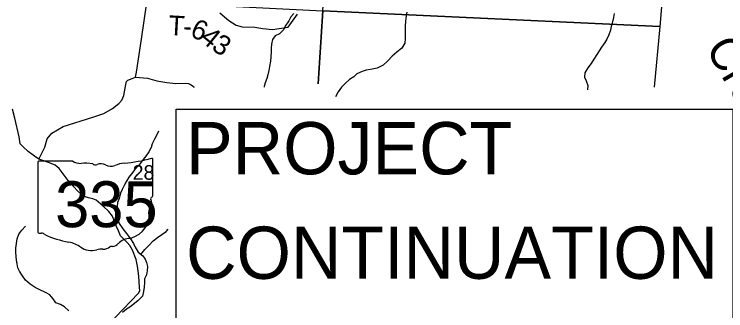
# Model space of a CAD drawing. Extents: x 0 to 40.8, y 0 to 22.
# Drawn here: x 4.714 to 6.756, y 18.326 to 19.177 of the extents above; entities that cross this region are included whole.
import ezdxf

# ---------------------------------------------------------------- set-up
doc = ezdxf.new("R2010")
doc.units = 0
for name, color, linetype in [('Default', 7, 'Continuous'), ('GM_X_County_Road', 7, 'Continuous'), ('GM_X_Minor_River', 7, 'Continuous'), ('GM_X_Minor_River_Text', 7, 'Continuous'), ('GM_X_Section', 7, 'Continuous'), ('GM_X_Section_Text', 7, 'Continuous'), ('GM_X_State_Location', 7, 'Continuous'), ('GM_X_State_Route', 7, 'Continuous'), ('GM_X_State_Shield', 7, 'Continuous'), ('GM_X_Township_Road', 7, 'Continuous'), ('GM_X_Township_Road_Text', 7, 'Continuous')]:
    doc.layers.add(name, color=color, linetype=linetype)

msp = doc.modelspace()

# ---------------------------------------------------------------- linework, layer by layer
at = {"layer": 'Default'}
msp.add_lwpolyline([(5.1786, 18.9041), (6.7762, 18.9041), (6.7762, 17.7808), (5.1786, 17.7808)], close=True, dxfattribs=at)
at = {"layer": 'GM_X_County_Road'}
msp.add_lwpolyline([(4.7852, 18.7609), (4.8017, 18.7952), (4.8083, 18.8191), (4.8222, 18.835), (4.8546, 18.8542), (4.9398, 18.8818), (4.9709, 18.8924), (4.9964, 18.9063), (5.0139, 18.9202), (5.0225, 18.9304), (5.0289, 18.9438), (5.0341, 18.9752), (5.0363, 18.9836), (5.0399, 18.9881), (5.0525, 18.9927), (5.0619, 18.9967), (5.0963, 18.993), (5.1237, 18.9854), (5.1525, 18.9811), (5.1776, 18.9784), (5.2051, 18.9794), (5.214, 18.9782), (5.2222, 18.9744), (5.2282, 18.9692), (5.2299, 18.9668)], dxfattribs=at)
at = {"layer": 'GM_X_Minor_River'}
for points in [[(5.5168, 19.1794), (5.5084, 19.1696), (5.5019, 19.1583), (5.492, 19.1424), (5.487, 19.1322), (5.4756, 19.1209), (5.4626, 19.1149), (5.4558, 19.1047), (5.4523, 19.0914), (5.4518, 19.0797), (5.4518, 19.0691), (5.4509, 19.055), (5.4497, 19.0422), (5.447, 19.027), (5.445, 19.0153), (5.4423, 19.0031), (5.4392, 18.9925), (5.4338, 18.9801), (5.4318, 18.9695), (5.4317, 18.9674)], [(5.8405, 19.1824), (5.8393, 19.1722), (5.8373, 19.157), (5.8361, 19.1422), (5.836, 19.1301), (5.8364, 19.1191), (5.8363, 19.107), (5.8347, 19.0937), (5.8263, 19.0797), (5.8122, 19.0677), (5.7989, 19.0564), (5.7851, 19.0421), (5.7726, 19.0308), (5.7559, 19.0225), (5.7464, 19.0199), (5.7362, 19.0181), (5.724, 19.0159), (5.7126, 19.0122), (5.6978, 19.0054), (5.6883, 18.9971), (5.6762, 18.99), (5.6636, 18.9779), (5.6537, 18.9674), (5.6438, 18.9538), (5.6365, 18.9402)], [(6.4361, 19.1789), (6.4337, 19.1679), (6.4298, 19.1516), (6.4271, 19.1414), (6.4248, 19.1312), (6.4201, 19.1179), (6.4148, 19.1058), (6.4094, 19.0956), (6.3995, 19.0824), (6.393, 19.0718), (6.3861, 19.0609), (6.3777, 19.0484), (6.3693, 19.0352), (6.3605, 19.0227), (6.3513, 19.0087), (6.3509, 18.9962), (6.3557, 18.986), (6.3606, 18.9723), (6.3595, 18.9595)], [(5.1278, 18.8416), (5.122, 18.8287), (5.1163, 18.8185), (5.1101, 18.8049), (5.107, 18.7939), (5.1009, 18.7818), (5.0914, 18.7697), (5.0841, 18.7599), (5.073, 18.7448), (5.0605, 18.7316), (5.0505, 18.7188), (5.0429, 18.709), (5.036, 18.698), (5.031, 18.6871), (5.0241, 18.6742), (5.0195, 18.6636), (5.0153, 18.6481), (5.011, 18.636), (5.0094, 18.6254), (5.0082, 18.6121), (5.0085, 18.6019), (5.0104, 18.5893), (5.0152, 18.5764), (5.0261, 18.5612), (5.0362, 18.5475), (5.0482, 18.5322), (5.0561, 18.5189), (5.0617, 18.5079), (5.0696, 18.4942), (5.0828, 18.4835), (5.0899, 18.4736), (5.0936, 18.4637), (5.0962, 18.4531), (5.0957, 18.4406), (5.0934, 18.4292), (5.0884, 18.4175), (5.0876, 18.4072), (5.0871, 18.3936), (5.0855, 18.3811), (5.0824, 18.3674), (5.0695, 18.355), (5.055, 18.343), (5.0455, 18.3358), (5.036, 18.3306), (5.025, 18.3204)], [(4.8713, 18.3255), (4.8589, 18.3373), (4.8468, 18.3438), (4.8339, 18.3484), (4.8257, 18.3602), (4.8159, 18.3713), (4.8057, 18.3771), (4.7861, 18.3863), (4.7744, 18.3928), (4.7601, 18.4024), (4.7469, 18.4134), (4.7375, 18.426), (4.7289, 18.4393), (4.7244, 18.4492), (4.7222, 18.4606), (4.7207, 18.4708), (4.72, 18.4811), (4.719, 18.4936), (4.7187, 18.5054), (4.7207, 18.5183), (4.723, 18.5323), (4.7276, 18.5459), (4.7357, 18.5572), (4.7463, 18.5689)], [(5.0778, 18.4875), (5.0889, 18.5016), (5.1004, 18.5133), (5.1133, 18.5261), (5.1251, 18.5356), (5.138, 18.5446), (5.1498, 18.5536), (5.1559, 18.5597)]]:
    msp.add_lwpolyline(points, dxfattribs=at)
at = {"layer": 'GM_X_Section'}
msp.add_lwpolyline([(5.6669, 20.1827), (6.1945, 20.1544), (6.6517, 20.1638), (6.5668, 19.1421), (5.5995, 19.1863)], close=True, dxfattribs=at)
for points in [[(5.1222, 18.2458), (4.9546, 18.2574), (4.4961, 18.3336), (4.6019, 19.2378), (5.5995, 19.1863), (5.5864, 18.978)], [(5.5863, 18.9775), (5.5995, 19.1863), (6.5668, 19.1421), (6.5505, 18.9672)]]:
    msp.add_lwpolyline(points, dxfattribs=at)
at = {"layer": 'GM_X_State_Route'}
msp.add_lwpolyline([(4.9824, 18.2839), (5.0708, 18.3759), (5.0743, 18.3831), (5.0732, 18.393), (5.0719, 18.4246), (5.0683, 18.4535), (5.0638, 18.4729), (5.0537, 18.4992), (5.0462, 18.513), (5.0383, 18.5214), (5.0285, 18.5314), (5.0194, 18.5409), (5.0131, 18.555), (5.0071, 18.5699), (5.0011, 18.584), (4.9958, 18.597), (4.9853, 18.6104), (4.9698, 18.6261), (4.9494, 18.6434), (4.9395, 18.6465), (4.9274, 18.65), (4.9134, 18.655), (4.8963, 18.6688), (4.8718, 18.696), (4.8549, 18.7186), (4.8432, 18.7339), (4.8315, 18.7434), (4.8155, 18.75), (4.7852, 18.7609), (4.7723, 18.7694), (4.7538, 18.7832), (4.7394, 18.7966), (4.7315, 18.8047), (4.7282, 18.8248), (4.7157, 18.8789), (4.7097, 18.9044)], dxfattribs=at)
at = {"layer": 'GM_X_State_Shield'}
for p, q in [((4.7823, 18.7516), (4.7823, 18.5514)), ((4.8821, 18.755), (4.7856, 18.755)), ((5.1119, 18.6553), (5.1119, 18.76)), ((5.1119, 18.6553), (5.1119, 18.6553))]:
    msp.add_line(p, q, dxfattribs=at)
for centre, major_axis, start_param, end_param in [((4.7861, 18.752), (0.00382, 0), 1.712693, 3.28349), ((4.9051, 18.7782), (0.037, 0), 4.042523, 4.731795), ((4.9174, 18.6427), (0.133, 0), 1.404758, 1.657858), ((4.9476, 18.753), (0.0107, 0), 3.836095, 5.185415), ((4.9632, 18.7299), (0.0222, 0), 0.950623, 2.079405), ((4.9919, 18.7616), (0.0267, 0), 4.081561, 5.145723), ((5.0391, 18.6939), (0.0703, 0), 1.699011, 2.107814), ((4.9945, 19.0278), (0.3495, 0), 4.814394, 5.042369), ((5.1083, 18.7604), (0.00367, 0), 6.141152, 7.989035), ((5.1111, 18.6476), (0.00568, 0), 1.883978, 3.671073), ((5.075, 18.6344), (0.0341, 0), 5.934695, 6.695948), ((5.108, 18.6549), (0.00393, 0), 5.05454, 6.418171), ((5.1251, 18.6115), (0.0248, 0), 2.387724, 3.262537), ((5.0141, 18.5981), (0.0874, 0), 5.101752, 6.440018), ((4.7862, 18.551), (0.00385, 0), 3.00124, 4.508301), ((4.7867, 18.5715), (0.0294, 0), 4.665946, 4.897461), ((4.7928, 18.5399), (0.0106, 0), 0.519207, 1.627899), ((4.9266, 18.7197), (0.2524, 0), 4.195997, 4.488961), ((4.8513, 18.4615), (0.079, 0), 0.823519, 1.323587), ((5.051, 18.4953), (0.0479, 0), 1.647645, 2.488434), ((4.9367, 18.5389), (0.0501, 0), 4.026481, 4.996735), ((4.9657, 18.4697), (0.0412, 0), 1.495662, 1.94098), ((4.9694, 18.5239), (0.0267, 0), 4.691044, 5.507374), ((4.9935, 18.5045), (0.00752, 0), 1.147584, 2.315152), ((4.9903, 18.532), (0.0282, 0), 4.937069, 5.64225)]:
    msp.add_ellipse(centre, major_axis=major_axis, ratio=0.8, start_param=start_param, end_param=end_param, dxfattribs=at)
at = {"layer": 'GM_X_Township_Road'}
for points in [[(5.0619, 18.9967), (5.0648, 19.0109), (5.0794, 19.1055), (5.0948, 19.2109)], [(5.3045, 19.1805), (5.3303, 19.1593), (5.3508, 19.1454), (5.368, 19.1408), (5.4044, 19.1401), (5.4276, 19.1361), (5.4554, 19.1328), (5.5006, 19.1398), (5.5269, 19.177)]]:
    msp.add_lwpolyline(points, dxfattribs=at)

# ---------------------------------------------------------------- texts
at = {"layer": 'Default'}
for s, p in [('PROJECT ', (5.2073, 18.7173)), ('CONTINUATION', (5.2073, 18.4173))]:
    msp.add_text(s, height=0.15, dxfattribs=at).set_placement(p)
at = {"layer": 'GM_X_Minor_River_Text'}
msp.add_text('Creek', height=0.0947, rotation=299.8895, dxfattribs=at).set_placement((6.6962, 19.0802))
at = {"layer": 'GM_X_Section_Text'}
msp.add_text('28', height=0.04186, rotation=0, dxfattribs=at).set_placement((5.0541, 18.7017))
at = {"layer": 'GM_X_State_Location'}
msp.add_text('335', height=0.000189, rotation=0, dxfattribs=at).set_placement((4.8766, 18.6244))
for s in ['s', 'r']:
    msp.add_text(s, height=0.000189, dxfattribs=at).set_placement((4.9434, 18.6382))
at = {"layer": 'GM_X_State_Shield'}
msp.add_text('335', height=0.13184, dxfattribs=at).set_placement((4.8315, 18.5655))
at = {"layer": 'GM_X_Township_Road_Text'}
for s, rotation, p in [('T', 356.784, (5.1552, 19.1173)), ('6', 336.0423, (5.2157, 19.1149)), ('-', 356.673, (5.1976, 19.1149)), ('4', 320.8647, (5.2443, 19.1027)), ('3', 327.7001, (5.2774, 19.0763))]:
    msp.add_text(s, height=0.0568, rotation=rotation, dxfattribs=at).set_placement(p)

doc.saveas('drawing.dxf')
